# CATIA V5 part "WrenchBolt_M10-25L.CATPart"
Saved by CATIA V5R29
Part number: WrenchBolt_M10-25L
Source: Unknown
Bounding box of the stored display mesh (mm): x -33 to 0, y -8 to 8, z -8 to 8
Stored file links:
  C:\가치같이\SmartFactory_BoxErectorConveyor\Boxing(over)\WrenchBolt_M10-25L.CATPart
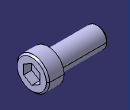
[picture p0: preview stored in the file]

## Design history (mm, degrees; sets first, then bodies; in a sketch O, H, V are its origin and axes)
Body1 (main body)
  Solid1 "PartBody": solid without history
